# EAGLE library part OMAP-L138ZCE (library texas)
OMAP-L138 Low-Power Applications Processor Auto generated by make-symbol-device-package-bsdl.ulp Rev. 30 Source: sprm377a.bsm http://focus.ti.com/lit/ds/symlink/omap-l138.pdf Connect-List generated from OMAPL138ZCE.DEV Variant '' with connect-device-split-symbol-03.ulp
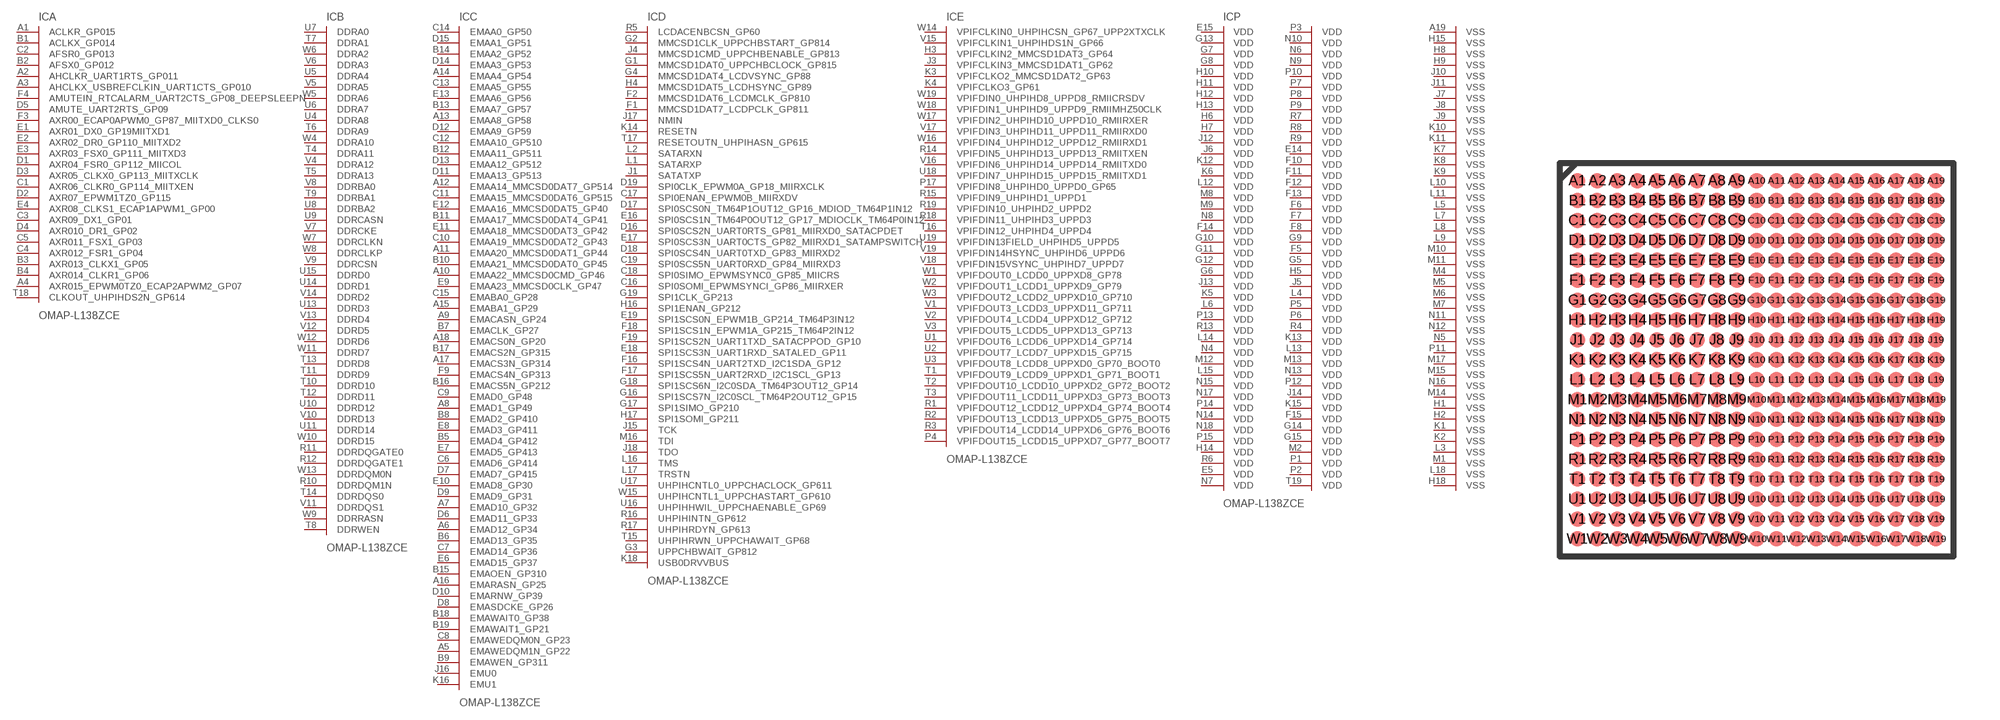
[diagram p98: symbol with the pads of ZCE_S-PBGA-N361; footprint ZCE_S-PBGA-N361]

Designator prefix IC; gates A=OMAP-L138_ZCE-A B=OMAP-L138_ZCE-B C=OMAP-L138_ZCE-C D=OMAP-L138_ZCE-D E=OMAP-L138_ZCE-E P=OMAP-L138_ZCE-P

## OMAP-L138ZCE (OC_FARNELL: unknown; OC_NEWARK: unknown)  [ZCE_S-PBGA-N361]
A1  A:ACLKR_GP015
A2  A:AHCLKR_UART1RTS_GP011
A3  A:AHCLKX_USBREFCLKIN_UART1CTS_GP010
A4  A:AXR015_EPWM0TZ0_ECAP2APWM2_GP07
A5  C:EMAWEDQM1N_GP22
A6  C:EMAD12_GP34
A7  C:EMAD10_GP32
A8  C:EMAD1_GP49
A9  C:EMACASN_GP24
A10  C:EMAA22_MMCSD0CMD_GP46
A11  C:EMAA20_MMCSD0DAT1_GP44
A12  C:EMAA14_MMCSD0DAT7_GP514
A13  C:EMAA8_GP58
A14  C:EMAA4_GP54
A15  C:EMABA1_GP29
A16  C:EMARASN_GP25
A17  C:EMACS3N_GP314
A18  C:EMACS0N_GP20
A19  P:VSS  pwr
B1  A:ACLKX_GP014
B2  A:AFSX0_GP012
B3  A:AXR013_CLKX1_GP05
B4  A:AXR014_CLKR1_GP06
B5  C:EMAD4_GP412
B6  C:EMAD13_GP35
B7  C:EMACLK_GP27
B8  C:EMAD2_GP410
B9  C:EMAWEN_GP311
B10  C:EMAA21_MMCSD0DAT0_GP45
B11  C:EMAA17_MMCSD0DAT4_GP41
B12  C:EMAA11_GP511
B13  C:EMAA7_GP57
B14  C:EMAA2_GP52
B15  C:EMAOEN_GP310
B16  C:EMACS5N_GP212
B17  C:EMACS2N_GP315
B18  C:EMAWAIT0_GP38
B19  C:EMAWAIT1_GP21
C1  A:AXR06_CLKR0_GP114_MIITXEN
C2  A:AFSR0_GP013
C3  A:AXR09_DX1_GP01
C4  A:AXR012_FSR1_GP04
C5  A:AXR011_FSX1_GP03
C6  C:EMAD6_GP414
C7  C:EMAD14_GP36
C8  C:EMAWEDQM0N_GP23
C9  C:EMAD0_GP48
C10  C:EMAA19_MMCSD0DAT2_GP43
C11  C:EMAA15_MMCSD0DAT6_GP515
C12  C:EMAA10_GP510
C13  C:EMAA5_GP55
C14  C:EMAA0_GP50
C15  C:EMABA0_GP28
C16  D:SPI0SOMI_EPWMSYNCI_GP86_MIIRXER
C17  D:SPI0ENAN_EPWM0B_MIIRXDV
C18  D:SPI0SIMO_EPWMSYNC0_GP85_MIICRS
C19  D:SPI0SCS5N_UART0RXD_GP84_MIIRXD3
D1  A:AXR04_FSR0_GP112_MIICOL
D2  A:AXR07_EPWM1TZ0_GP115
D3  A:AXR05_CLKX0_GP113_MIITXCLK
D4  A:AXR010_DR1_GP02
D5  A:AMUTE_UART2RTS_GP09
D6  C:EMAD11_GP33
D7  C:EMAD7_GP415
D8  C:EMASDCKE_GP26
D9  C:EMAD9_GP31
D10  C:EMARNW_GP39
D11  C:EMAA13_GP513
D12  C:EMAA9_GP59
D13  C:EMAA12_GP512
D14  C:EMAA3_GP53
D15  C:EMAA1_GP51
D16  D:SPI0SCS2N_UART0RTS_GP81_MIIRXD0_SATACPDET
D17  D:SPI0SCS0N_TM64P1OUT12_GP16_MDIOD_TM64P1IN12
D18  D:SPI0SCS4N_UART0TXD_GP83_MIIRXD2
D19  D:SPI0CLK_EPWM0A_GP18_MIIRXCLK
E1  A:AXR01_DX0_GP19MIITXD1
E2  A:AXR02_DR0_GP110_MIITXD2
E3  A:AXR03_FSX0_GP111_MIITXD3
E4  A:AXR08_CLKS1_ECAP1APWM1_GP00
E5  P:VDD  pwr
E6  C:EMAD15_GP37
E7  C:EMAD5_GP413
E8  C:EMAD3_GP411
E9  C:EMAA23_MMCSD0CLK_GP47
E10  C:EMAD8_GP30
E11  C:EMAA18_MMCSD0DAT3_GP42
E12  C:EMAA16_MMCSD0DAT5_GP40
E13  C:EMAA6_GP56
E14  P:VDD  pwr
E15  P:VDD  pwr
E16  D:SPI0SCS1N_TM64P0OUT12_GP17_MDIOCLK_TM64P0IN12
E17  D:SPI0SCS3N_UART0CTS_GP82_MIIRXD1_SATAMPSWITCH
E18  D:SPI1SCS3N_UART1RXD_SATALED_GP11
E19  D:SPI1SCS0N_EPWM1B_GP214_TM64P3IN12
F1  D:MMCSD1DAT7_LCDPCLK_GP811
F2  D:MMCSD1DAT6_LCDMCLK_GP810
F3  A:AXR00_ECAP0APWM0_GP87_MIITXD0_CLKS0
F4  A:AMUTEIN_RTCALARM_UART2CTS_GP08_DEEPSLEEPN
F5  P:VDD  pwr
F6  P:VDD  pwr
F7  P:VDD  pwr
F8  P:VDD  pwr
F9  C:EMACS4N_GP313
F10  P:VDD  pwr
F11  P:VDD  pwr
F12  P:VDD  pwr
F13  P:VDD  pwr
F14  P:VDD  pwr
F15  P:VDD  pwr
F16  D:SPI1SCS4N_UART2TXD_I2C1SDA_GP12
F17  D:SPI1SCS5N_UART2RXD_I2C1SCL_GP13
F18  D:SPI1SCS1N_EPWM1A_GP215_TM64P2IN12
F19  D:SPI1SCS2N_UART1TXD_SATACPPOD_GP10
G1  D:MMCSD1DAT0_UPPCHBCLOCK_GP815
G2  D:MMCSD1CLK_UPPCHBSTART_GP814
G3  D:UPPCHBWAIT_GP812
G4  D:MMCSD1DAT4_LCDVSYNC_GP88
G5  P:VDD  pwr
G6  P:VDD  pwr
G7  P:VDD  pwr
G8  P:VDD  pwr
G9  P:VDD  pwr
G10  P:VDD  pwr
G11  P:VDD  pwr
G12  P:VDD  pwr
G13  P:VDD  pwr
G14  P:VDD  pwr
G15  P:VDD  pwr
G16  D:SPI1SCS7N_I2C0SCL_TM64P2OUT12_GP15
G17  D:SPI1SIMO_GP210
G18  D:SPI1SCS6N_I2C0SDA_TM64P3OUT12_GP14
G19  D:SPI1CLK_GP213
H1  P:VSS  pwr
H2  P:VSS  pwr
H3  E:VPIFCLKIN2_MMCSD1DAT3_GP64
H4  D:MMCSD1DAT5_LCDHSYNC_GP89
H5  P:VDD  pwr
H6  P:VDD  pwr
H7  P:VDD  pwr
H8  P:VSS  pwr
H9  P:VSS  pwr
H10  P:VDD  pwr
H11  P:VDD  pwr
H12  P:VDD  pwr
H13  P:VDD  pwr
H14  P:VDD  pwr
H15  P:VSS  pwr
H16  D:SPI1ENAN_GP212
H17  D:SPI1SOMI_GP211
H18  P:VSS  pwr
J1  D:SATATXP  hiz
J3  E:VPIFCLKIN3_MMCSD1DAT1_GP62
J4  D:MMCSD1CMD_UPPCHBENABLE_GP813
J5  P:VDD  pwr
J6  P:VDD  pwr
J7  P:VSS  pwr
J8  P:VSS  pwr
J9  P:VSS  pwr
J10  P:VSS  pwr
J11  P:VSS  pwr
J12  P:VDD  pwr
J13  P:VDD  pwr
J14  P:VDD  pwr
J15  D:TCK  in
J16  C:EMU0
J17  D:NMIN  in
J18  D:TDO  out
K1  P:VSS  pwr
K2  P:VSS  pwr
K3  E:VPIFCLKO2_MMCSD1DAT2_GP63
K4  E:VPIFCLKO3_GP61
K5  P:VDD  pwr
K6  P:VDD  pwr
K7  P:VSS  pwr
K8  P:VSS  pwr
K9  P:VSS  pwr
K10  P:VSS  pwr
K11  P:VSS  pwr
K12  P:VDD  pwr
K13  P:VDD  pwr
K14  D:RESETN  in
K15  P:VDD  pwr
K16  C:EMU1
K18  D:USB0DRVVBUS
L1  D:SATARXP  in
L2  D:SATARXN  in
L3  P:VSS  pwr
L4  P:VDD  pwr
L5  P:VSS  pwr
L6  P:VDD  pwr
L7  P:VSS  pwr
L8  P:VSS  pwr
L9  P:VSS  pwr
L10  P:VSS  pwr
L11  P:VSS  pwr
L12  P:VDD  pwr
L13  P:VDD  pwr
L14  P:VDD  pwr
L15  P:VDD  pwr
L16  D:TMS  in
L17  D:TRSTN  in
L18  P:VSS  pwr
M1  P:VSS  pwr
M2  P:VDD  pwr
M4  P:VSS  pwr
M5  P:VSS  pwr
M6  P:VSS  pwr
M7  P:VSS  pwr
M8  P:VDD  pwr
M9  P:VDD  pwr
M10  P:VSS  pwr
M11  P:VSS  pwr
M12  P:VDD  pwr
M13  P:VDD  pwr
M14  P:VSS  pwr
M15  P:VSS  pwr
M16  D:TDI  in
M17  P:VSS  pwr
N4  P:VDD  pwr
N5  P:VSS  pwr
N6  P:VDD  pwr
N7  P:VDD  pwr
N8  P:VDD  pwr
N9  P:VDD  pwr
N10  P:VDD  pwr
N11  P:VSS  pwr
N12  P:VSS  pwr
N13  P:VDD  pwr
N14  P:VDD  pwr
N15  P:VDD  pwr
N16  P:VSS  pwr
N17  P:VDD  pwr
N18  P:VDD  pwr
P1  P:VDD  pwr
P2  P:VDD  pwr
P3  P:VDD  pwr
P4  E:VPIFDOUT15_LCDD15_UPPXD7_GP77_BOOT7
P5  P:VDD  pwr
P6  P:VDD  pwr
P7  P:VDD  pwr
P8  P:VDD  pwr
P9  P:VDD  pwr
P10  P:VDD  pwr
P11  P:VSS  pwr
P12  P:VDD  pwr
P13  P:VDD  pwr
P14  P:VDD  pwr
P15  P:VDD  pwr
P17  E:VPIFDIN8_UHPIHD0_UPPD0_GP65
R1  E:VPIFDOUT12_LCDD12_UPPXD4_GP74_BOOT4
R2  E:VPIFDOUT13_LCDD13_UPPXD5_GP75_BOOT5
R3  E:VPIFDOUT14_LCDD14_UPPXD6_GP76_BOOT6
R4  P:VDD  pwr
R5  D:LCDACENBCSN_GP60
R6  P:VDD  pwr
R7  P:VDD  pwr
R8  P:VDD  pwr
R9  P:VDD  pwr
R10  B:DDRDQM1N
R11  B:DDRDQGATE0
R12  B:DDRDQGATE1
R13  P:VDD  pwr
R14  E:VPIFDIN5_UHPIHD13_UPPD13_RMIITXEN
R15  E:VPIFDIN9_UHPIHD1_UPPD1
R16  D:UHPIHINTN_GP612
R17  D:UHPIHRDYN_GP613
R18  E:VPIFDIN11_UHPIHD3_UPPD3
R19  E:VPIFDIN10_UHPIHD2_UPPD2
T1  E:VPIFDOUT9_LCDD9_UPPXD1_GP71_BOOT1
T2  E:VPIFDOUT10_LCDD10_UPPXD2_GP72_BOOT2
T3  E:VPIFDOUT11_LCDD11_UPPXD3_GP73_BOOT3
T4  B:DDRA11
T5  B:DDRA13
T6  B:DDRA9
T7  B:DDRA1
T8  B:DDRWEN
T9  B:DDRBA1
T10  B:DDRD10
T11  B:DDRD9
T12  B:DDRD11
T13  B:DDRD8
T14  B:DDRDQS0
T15  D:UHPIHRWN_UPPCHAWAIT_GP68
T16  E:VPIFDIN12_UHPIHD4_UPPD4
T17  D:RESETOUTN_UHPIHASN_GP615
T18  A:CLKOUT_UHPIHDS2N_GP614
T19  P:VDD  pwr
U1  E:VPIFDOUT6_LCDD6_UPPXD14_GP714
U2  E:VPIFDOUT7_LCDD7_UPPXD15_GP715
U3  E:VPIFDOUT8_LCDD8_UPPXD0_GP70_BOOT0
U4  B:DDRA8
U5  B:DDRA4
U6  B:DDRA7
U7  B:DDRA0
U8  B:DDRBA2
U9  B:DDRCASN
U10  B:DDRD12
U11  B:DDRD14
U13  B:DDRD3
U14  B:DDRD1
U15  B:DDRD0
U16  D:UHPIHHWIL_UPPCHAENABLE_GP69
U17  D:UHPIHCNTL0_UPPCHACLOCK_GP611
U18  E:VPIFDIN7_UHPIHD15_UPPD15_RMIITXD1
U19  E:VPIFDIN13FIELD_UHPIHD5_UPPD5
V1  E:VPIFDOUT3_LCDD3_UPPXD11_GP711
V2  E:VPIFDOUT4_LCDD4_UPPXD12_GP712
V3  E:VPIFDOUT5_LCDD5_UPPXD13_GP713
V4  B:DDRA12
V5  B:DDRA5
V6  B:DDRA3
V7  B:DDRCKE
V8  B:DDRBA0
V9  B:DDRCSN
V10  B:DDRD13
V11  B:DDRDQS1
V12  B:DDRD5
V13  B:DDRD4
V14  B:DDRD2
V15  E:VPIFCLKIN1_UHPIHDS1N_GP66
V16  E:VPIFDIN6_UHPIHD14_UPPD14_RMIITXD0
V17  E:VPIFDIN3_UHPIHD11_UPPD11_RMIIRXD0
V18  E:VPIFDIN15VSYNC_UHPIHD7_UPPD7
V19  E:VPIFDIN14HSYNC_UHPIHD6_UPPD6
W1  E:VPIFDOUT0_LCDD0_UPPXD8_GP78
W2  E:VPIFDOUT1_LCDD1_UPPXD9_GP79
W3  E:VPIFDOUT2_LCDD2_UPPXD10_GP710
W4  B:DDRA10
W5  B:DDRA6
W6  B:DDRA2
W7  B:DDRCLKN
W8  B:DDRCLKP
W9  B:DDRRASN
W10  B:DDRD15
W11  B:DDRD7
W12  B:DDRD6
W13  B:DDRDQM0N
W14  E:VPIFCLKIN0_UHPIHCSN_GP67_UPP2XTXCLK
W15  D:UHPIHCNTL1_UPPCHASTART_GP610
W16  E:VPIFDIN4_UHPIHD12_UPPD12_RMIIRXD1
W17  E:VPIFDIN2_UHPIHD10_UPPD10_RMIIRXER
W18  E:VPIFDIN1_UHPIHD9_UPPD9_RMIIMHZ50CLK
W19  E:VPIFDIN0_UHPIHD8_UPPD8_RMIICRSDV

## Footprint ZCE_S-PBGA-N361 (pad centres in mm)
ZCE (S-PBGA-N361) Auto generated by make-symbol-device-package-bsdl.ulp Rev. 30 Source: sprm377a.bsm http://focus.ti.com/lit/ds/symlink/omap-l138.pdf
smd 0.5 x 0.5: A1 -5.85,5.85; A2 -5.2,5.85; A3 -4.55,5.85; A4 -3.9,5.85; A5 -3.25,5.85; A6 -2.6,5.85; A7 -1.95,5.85; A8 -1.3,5.85; A9 -0.65,5.85; A10 0,5.85; A11 0.65,5.85; A12 1.3,5.85; A13 1.95,5.85; A14 2.6,5.85; A15 3.25,5.85; A16 3.9,5.85; A17 4.55,5.85; A18 5.2,5.85; A19 5.85,5.85; B1 -5.85,5.2; B2 -5.2,5.2; B3 -4.55,5.2; B4 -3.9,5.2; B5 -3.25,5.2; B6 -2.6,5.2; B7 -1.95,5.2; B8 -1.3,5.2; B9 -0.65,5.2; B10 0,5.2; B11 0.65,5.2; B12 1.3,5.2; B13 1.95,5.2; B14 2.6,5.2; B15 3.25,5.2; B16 3.9,5.2; B17 4.55,5.2; B18 5.2,5.2; B19 5.85,5.2; C1 -5.85,4.55; C2 -5.2,4.55; C3 -4.55,4.55; C4 -3.9,4.55; C5 -3.25,4.55; C6 -2.6,4.55; C7 -1.95,4.55; C8 -1.3,4.55; C9 -0.65,4.55; C10 0,4.55; C11 0.65,4.55; C12 1.3,4.55; C13 1.95,4.55; C14 2.6,4.55; C15 3.25,4.55; C16 3.9,4.55; C17 4.55,4.55; C18 5.2,4.55; C19 5.85,4.55; D1 -5.85,3.9; D2 -5.2,3.9; D3 -4.55,3.9; D4 -3.9,3.9; D5 -3.25,3.9; D6 -2.6,3.9; D7 -1.95,3.9; D8 -1.3,3.9; D9 -0.65,3.9; D10 0,3.9; D11 0.65,3.9; D12 1.3,3.9; D13 1.95,3.9; D14 2.6,3.9; D15 3.25,3.9; D16 3.9,3.9; D17 4.55,3.9; D18 5.2,3.9; D19 5.85,3.9; E1 -5.85,3.25; E2 -5.2,3.25; E3 -4.55,3.25; E4 -3.9,3.25; E5 -3.25,3.25; E6 -2.6,3.25; E7 -1.95,3.25; E8 -1.3,3.25; E9 -0.65,3.25; E10 0,3.25; E11 0.65,3.25; E12 1.3,3.25; E13 1.95,3.25; E14 2.6,3.25; E15 3.25,3.25; E16 3.9,3.25; E17 4.55,3.25; E18 5.2,3.25; E19 5.85,3.25; F1 -5.85,2.6; F2 -5.2,2.6; F3 -4.55,2.6; F4 -3.9,2.6; F5 -3.25,2.6; F6 -2.6,2.6; F7 -1.95,2.6; F8 -1.3,2.6; F9 -0.65,2.6; F10 0,2.6; F11 0.65,2.6; F12 1.3,2.6; F13 1.95,2.6; F14 2.6,2.6; F15 3.25,2.6; F16 3.9,2.6; F17 4.55,2.6; F18 5.2,2.6; F19 5.85,2.6; G1 -5.85,1.95; G2 -5.2,1.95; G3 -4.55,1.95; G4 -3.9,1.95; G5 -3.25,1.95; G6 -2.6,1.95; G7 -1.95,1.95; G8 -1.3,1.95; G9 -0.65,1.95; G10 0,1.95; G11 0.65,1.95; G12 1.3,1.95; G13 1.95,1.95; G14 2.6,1.95; G15 3.25,1.95; G16 3.9,1.95; G17 4.55,1.95; G18 5.2,1.95; G19 5.85,1.95; H1 -5.85,1.3; H2 -5.2,1.3; H3 -4.55,1.3; H4 -3.9,1.3; H5 -3.25,1.3; H6 -2.6,1.3; H7 -1.95,1.3; H8 -1.3,1.3; H9 -0.65,1.3; H10 0,1.3; H11 0.65,1.3; H12 1.3,1.3; H13 1.95,1.3; H14 2.6,1.3; H15 3.25,1.3; H16 3.9,1.3; H17 4.55,1.3; H18 5.2,1.3; H19 5.85,1.3; J1 -5.85,0.65; J2 -5.2,0.65; J3 -4.55,0.65; J4 -3.9,0.65; J5 -3.25,0.65; J6 -2.6,0.65; J7 -1.95,0.65; J8 -1.3,0.65; J9 -0.65,0.65; J10 0,0.65; J11 0.65,0.65; J12 1.3,0.65; J13 1.95,0.65; J14 2.6,0.65; J15 3.25,0.65; J16 3.9,0.65; J17 4.55,0.65; J18 5.2,0.65; J19 5.85,0.65; K1 -5.85,0; K2 -5.2,0; K3 -4.55,0; K4 -3.9,0; K5 -3.25,0; K6 -2.6,0; K7 -1.95,0; K8 -1.3,0; K9 -0.65,0; K10 0,0; K11 0.65,0; K12 1.3,0; K13 1.95,0; K14 2.6,0; K15 3.25,0; K16 3.9,0; K17 4.55,0; K18 5.2,0; K19 5.85,0; L1 -5.85,-0.65; L2 -5.2,-0.65; L3 -4.55,-0.65; L4 -3.9,-0.65; L5 -3.25,-0.65; L6 -2.6,-0.65; L7 -1.95,-0.65; L8 -1.3,-0.65; L9 -0.65,-0.65; L10 0,-0.65; L11 0.65,-0.65; L12 1.3,-0.65; L13 1.95,-0.65; L14 2.6,-0.65; L15 3.25,-0.65; L16 3.9,-0.65; L17 4.55,-0.65; L18 5.2,-0.65; L19 5.85,-0.65; M1 -5.85,-1.3; M2 -5.2,-1.3; M3 -4.55,-1.3; M4 -3.9,-1.3; M5 -3.25,-1.3; M6 -2.6,-1.3; M7 -1.95,-1.3; M8 -1.3,-1.3; M9 -0.65,-1.3; M10 0,-1.3; M11 0.65,-1.3; M12 1.3,-1.3; M13 1.95,-1.3; M14 2.6,-1.3; M15 3.25,-1.3; M16 3.9,-1.3; M17 4.55,-1.3; M18 5.2,-1.3; M19 5.85,-1.3; N1 -5.85,-1.95; N2 -5.2,-1.95; N3 -4.55,-1.95; N4 -3.9,-1.95; N5 -3.25,-1.95; N6 -2.6,-1.95; N7 -1.95,-1.95; N8 -1.3,-1.95; N9 -0.65,-1.95; N10 0,-1.95; N11 0.65,-1.95; N12 1.3,-1.95; N13 1.95,-1.95; N14 2.6,-1.95; N15 3.25,-1.95; N16 3.9,-1.95; N17 4.55,-1.95; N18 5.2,-1.95; N19 5.85,-1.95; P1 -5.85,-2.6; P2 -5.2,-2.6; P3 -4.55,-2.6; P4 -3.9,-2.6; P5 -3.25,-2.6; P6 -2.6,-2.6; P7 -1.95,-2.6; P8 -1.3,-2.6; P9 -0.65,-2.6; P10 0,-2.6; P11 0.65,-2.6; P12 1.3,-2.6; P13 1.95,-2.6; P14 2.6,-2.6; P15 3.25,-2.6; P16 3.9,-2.6; P17 4.55,-2.6; P18 5.2,-2.6; P19 5.85,-2.6; R1 -5.85,-3.25; R2 -5.2,-3.25; R3 -4.55,-3.25; R4 -3.9,-3.25; R5 -3.25,-3.25; R6 -2.6,-3.25; R7 -1.95,-3.25; R8 -1.3,-3.25; R9 -0.65,-3.25; R10 0,-3.25; R11 0.65,-3.25; R12 1.3,-3.25; R13 1.95,-3.25; R14 2.6,-3.25; R15 3.25,-3.25; R16 3.9,-3.25; R17 4.55,-3.25; R18 5.2,-3.25; R19 5.85,-3.25; T1 -5.85,-3.9; T2 -5.2,-3.9; T3 -4.55,-3.9; T4 -3.9,-3.9; T5 -3.25,-3.9; T6 -2.6,-3.9; T7 -1.95,-3.9; T8 -1.3,-3.9; T9 -0.65,-3.9; T10 0,-3.9; T11 0.65,-3.9; T12 1.3,-3.9; T13 1.95,-3.9; T14 2.6,-3.9; T15 3.25,-3.9; T16 3.9,-3.9; T17 4.55,-3.9; T18 5.2,-3.9; T19 5.85,-3.9; U1 -5.85,-4.55; U2 -5.2,-4.55; U3 -4.55,-4.55; U4 -3.9,-4.55; U5 -3.25,-4.55; U6 -2.6,-4.55; U7 -1.95,-4.55; U8 -1.3,-4.55; U9 -0.65,-4.55; U10 0,-4.55; U11 0.65,-4.55; U12 1.3,-4.55; U13 1.95,-4.55; U14 2.6,-4.55; U15 3.25,-4.55; U16 3.9,-4.55; U17 4.55,-4.55; U18 5.2,-4.55; U19 5.85,-4.55; V1 -5.85,-5.2; V2 -5.2,-5.2; V3 -4.55,-5.2; V4 -3.9,-5.2; V5 -3.25,-5.2; V6 -2.6,-5.2; V7 -1.95,-5.2; V8 -1.3,-5.2; V9 -0.65,-5.2; V10 0,-5.2; V11 0.65,-5.2; V12 1.3,-5.2; V13 1.95,-5.2; V14 2.6,-5.2; V15 3.25,-5.2; V16 3.9,-5.2; V17 4.55,-5.2; V18 5.2,-5.2; V19 5.85,-5.2; W1 -5.85,-5.85; W2 -5.2,-5.85; W3 -4.55,-5.85; W4 -3.9,-5.85; W5 -3.25,-5.85; W6 -2.6,-5.85; W7 -1.95,-5.85; W8 -1.3,-5.85; W9 -0.65,-5.85; W10 0,-5.85; W11 0.65,-5.85; W12 1.3,-5.85; W13 1.95,-5.85; W14 2.6,-5.85; W15 3.25,-5.85; W16 3.9,-5.85; W17 4.55,-5.85; W18 5.2,-5.85; W19 5.85,-5.85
